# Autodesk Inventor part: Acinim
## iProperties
Created: 2007-04
Part Number: Acinim
Material: Steel, Mild
Document SubType Name: Sheet Metal
Designer: David
Density: 1 g/cm^3
Sheet Metal Rule: 1.2 mm Steel, Mild
Author: David
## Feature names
1. Mirror1
2. Mirror3
3. Corner Round1
4. Hole1
5. Mirror4
6. Plate1
7. Plate2
8. Bend1
9. Plate3
10. Bend2
11. Plate8
12. Bend7
13. Plate9
14. Bend8
15. Plate10
16. Bend9
17. Plate11
18. Bend10
